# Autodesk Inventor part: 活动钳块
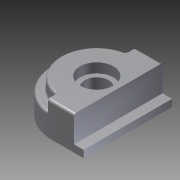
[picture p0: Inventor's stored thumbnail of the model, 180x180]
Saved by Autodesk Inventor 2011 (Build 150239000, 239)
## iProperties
Created: 2013-11
Part Number: 活动钳块
Document SubType Name: Modeling
Designer: user
Density: 1 g/cm^3
Author: user
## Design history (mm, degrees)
sketch "草图1"
  geometry: L1 (0, 37)-(26, 37); L2 (26, 37)-(26, -37); L3 (26, -37)-(0, -37); A1 r 37 centre (0, 0) between (0, 37) and (0, -37); 1 further point
  constraints: 6 end point, 2 point on circle, 2 tangent, 1 centre point, 1 coincident, 1 horizontal, 1 perpendicular
  dimensions: "d0" = 74 diameter of A1; "d1" = 26 distance of L1.start L1.end; "d2" = 74 distance of L1.end L2.end
extrude "拉伸1" new body sketch "草图1" distance "d3" = 18; taper "d4" = 0 deg
sketch "草图2"
  geometry: L1 (0, 37)-(26, 37) reference; L2 (26, -37)-(0, -37) reference; L3 (26, 37)-(26, -37) reference; L4 (18, 37)-(18, -37); L5 (-4, 36.783)-(-4, 29.732); L6 (-4, -29.732)-(-4, -36.783); A1 r 37 centre (0, 0) between (0, 37) and (0, -37) reference; A2 r 30 centre (0, 0) between (-4, 29.732) and (-4, -29.732)
  constraints: 6 end point, 4 point on circle, 2 parallel, 2 point on line, 1 centre point, 1 coincident, 1 collinear
  dimensions: "d5" = 60 diameter of A2; "d6" = 8 distance between parallel lines of L3 L4; "d7" = 30 distance between parallel lines of L3 L5
extrude "拉伸2" join sketch "草图2" distance "d8" = 10; taper "d9" = 0 deg
sketch "草图3"
  geometry: L1 (18, 37)-(18, -37) reference; L2 (26, -37)-(18, -37) reference; L3 (26, 37)-(26, -37) reference; L4 (18, 37)-(26, 37) reference; 1 further point
extrude "拉伸3" cut sketch "草图3" distance "d10" = 12; taper "d11" = 0 deg
hole "Hole1" diameter "d14" = 20; stored, may be unused: countersink angle "d18" = 90 deg, drill point angle "d20" = 0 deg; dims "d12" = 10, "d13" = 10, "d15" = 6, "d16" = 28, "d17" = 8, "d19" = 8
fillet "圆角1" dims "d21" = 2
fillet "圆角2" dims "d22" = 2
fillet "圆角3" dims "d23" = 2
node "实体1"
